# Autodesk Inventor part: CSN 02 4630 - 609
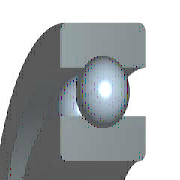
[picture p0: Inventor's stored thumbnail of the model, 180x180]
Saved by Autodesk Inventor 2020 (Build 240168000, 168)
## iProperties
Created: 2019-01
Part Number: CSN 02 4630 - 609
Material: Ocel, měkká
Description: Kuličková ložiska jednořadá
Document SubType Name: Modeling
Standard: CSN 02 4630
Designer: doma
Standards Organization: CSN
Language: cs-CZ
Size Designation: 609
Categories: <MemberInstance><Categories><Category DisplayName="Součásti hřídele" InternalName="7f7aeb1f-a693-4053-b835-cee3144e0d98" Mnemonic="SHFT"><Category DisplayName="
Density: 7.85 g/cm^3
Appearance: Pololeštěná
Mass: 14.5507 g
Surface Area: 23.044 cm^2
Volume: 1.8536 cm^3
IsCustomPart: 0
Author: doma
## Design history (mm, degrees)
sketch "Náčrt" dims "d0" = 3.9 (= -0.26 x WD + 0.26 x BD)
  geometry: L1 (1.55, 8.25)-(5.45, 8.25); L2 (3.5, 8.25)-(3.5, 6.3); L3 (3.5, 8.25)-(3.5, 10.2); L4 (2.051, 6.945)-(0, 6.945); L5 (0, 4.5)-(7, 4.5); L6 (2.051, 9.555)-(0, 9.555); L7 (0, 12)-(7, 12); L8 (7, 4.5)-(7, 6.945); L9 (4.949, 6.945)-(7, 6.945); L10 (4.949, 9.555)-(7, 9.555); L11 (7, 12)-(7, 9.555); L12 (-1.4, 0)-(8.4, 0) reference; L13 (0, -0.3)-(0, 5.3) reference
  constraints: 22 end point, 4 point on line, 2 collinear, 2 perpendicular, 2 symmetric about line, 1 midpoint, 1 parallel, 14 other
  dimensions: "d9" = 9 diameter of L5 L12 (= WD); "d11" = 24 diameter of L7 L12 (= BD); "d12" = 7 distance between parallel lines of L8 L13 (= KB); "d13" = 13.89 diameter of L9 L12 (= 0.326 x BD + 0.674 x WD)
revolve "Těleso" stored, may be unused: angle "d6" = 90 deg
revolve "Kulička" stored, may be unused: angle "d7" = 90 deg
pattern_circular "Kuličky" dims angle "d3" = 360 deg
body "Solid1"
fillet "Zaoblení1" dims "d1" = 0.3 (= KRS)
other parameters: "WD" = 9 [user parameter; used in 5 equation terms], "BD" = 24 [user parameter; used in 5 equation terms], "KB" = 7 [user parameter; used in 1 equation term], "KRS" = 0.3 [user parameter; used in 1 equation term], "d4" = 0, "d5" = 0, "d8" = 0, "d14" = 0, "d15" = 0, "BBA" = 0 [user parameter], "BC0" = 1660000 [user parameter], "BC" = 3710000 [user parameter], "BR" = 12 (= 0.5 x BD) [user parameter], "WR" = 4.5 (= 0.5 x WD) [user parameter]
